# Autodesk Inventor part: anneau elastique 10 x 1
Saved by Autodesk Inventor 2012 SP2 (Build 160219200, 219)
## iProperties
Created: 2013-04
Part Number: anneau elastique 10 x 1
Material: Default
Document SubType Name: Modeling
Designer: papa
Density: 1 g/cm^3
Mass: 0.0571857 g
Surface Area: 2.04084 cm^2
Volume: 0.0571857 cm^3
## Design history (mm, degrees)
node "anneau elastique 10 x 11"
node "anneau elastique 10 x 1"
node "Base1"
